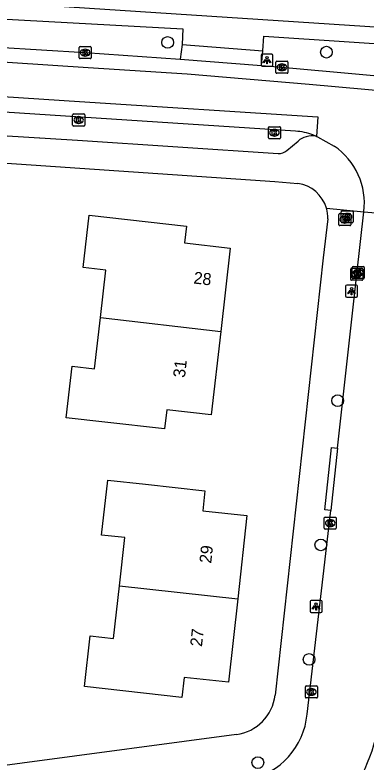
# Model space of a CAD drawing. Extents: x 162398 to 163643, y 386453 to 387397.
# Drawn here: x 162822.3 to 162851.5, y 386535 to 386597.2 of the extents above; entities that cross this region are included whole.
import ezdxf

# ---------------------------------------------------------------- set-up
doc = ezdxf.new("R2010")
doc.units = 0
for name, color, linetype in [('IMGEO_Boom', 7, 'Continuous'), ('IMGEO_Brandkraan', 7, 'Continuous'), ('IMGEO_Kolk', 7, 'Continuous'), ('IMGEO_Lichtpunt', 7, 'Continuous'), ('IMGEO_Pand', 7, 'Continuous'), ('IMGEO_Pand_nummerreeks', 7, 'Continuous'), ('IMGEO_Rijbaan_lokaal_gesloten', 7, 'Continuous'), ('IMGEO_Rijbaan_lokaal_open', 7, 'Continuous'), ('IMGEO_Voetpad_open', 7, 'Continuous')]:
    doc.layers.add(name, color=color, linetype=linetype)

msp = doc.modelspace()

# ---------------------------------------------------------------- linework, layer by layer
at = {"layer": 'IMGEO_Boom'}
for centre in [(162835.01, 386594.914), (162848.244, 386594.102), (162849.181, 386565.089), (162847.78, 386553.08), (162846.801, 386543.543), (162842.53, 386534.956)]:
    msp.add_circle(centre, 0.489, dxfattribs=at)
at = {"layer": 'IMGEO_Brandkraan'}
for p, q in [((162849.54, 386580.896), (162850.392, 386580.896)), ((162849.275, 386579.733), (162849.275, 386580.585)), ((162849.35, 386580.659), (162850.202, 386580.659)), ((162849.465, 386579.97), (162849.465, 386580.822)), ((162849.763, 386580.439), (162849.788, 386580.439)), ((162849.953, 386580.676), (162849.978, 386580.676)), ((162850.276, 386580.585), (162850.276, 386579.733)), ((162850.466, 386580.822), (162850.466, 386579.97)), ((162850.202, 386579.659), (162849.35, 386579.659)), ((162850.392, 386579.896), (162849.54, 386579.896)), ((162849.786, 386579.879), (162849.761, 386579.879)), ((162849.976, 386580.116), (162849.951, 386580.116))]:
    msp.add_line(p, q, dxfattribs=at)
for points in [[(162849.54, 386580.896), (162850.392, 386580.896)], [(162849.275, 386579.733), (162849.275, 386580.585)], [(162849.35, 386580.659), (162850.202, 386580.659)], [(162849.465, 386579.97), (162849.465, 386580.822)], [(162849.623, 386580.359), (162849.623, 386579.959), (162849.836, 386579.959)], [(162849.854, 386580.359), (162849.623, 386580.359)], [(162849.802, 386580.278), (162849.748, 386580.278), (162849.748, 386580.202)], [(162849.813, 386580.596), (162849.813, 386580.196), (162850.026, 386580.196)], [(162850.044, 386580.596), (162849.813, 386580.596)], [(162849.992, 386580.515), (162849.938, 386580.515), (162849.938, 386580.439)], [(162849.938, 386580.439), (162849.991, 386580.439)], [(162850, 386580.363), (162849.938, 386580.363), (162849.938, 386580.282)], [(162849.938, 386580.282), (162850, 386580.282)], [(162850.276, 386580.585), (162850.276, 386579.733)], [(162850.466, 386580.822), (162850.466, 386579.97)], [(162850.202, 386579.659), (162849.35, 386579.659)], [(162850.392, 386579.896), (162849.54, 386579.896)], [(162849.748, 386580.202), (162849.801, 386580.202)], [(162849.81, 386580.126), (162849.748, 386580.126), (162849.748, 386580.045)], [(162849.748, 386580.045), (162849.81, 386580.045)]]:
    msp.add_lwpolyline(points, dxfattribs=at)
for centre, radius, start, end in [((162849.542, 386580.82), 0.0765, 91.55205, 178.44795), ((162849.542, 386580.82), 0.0765, 91.55205, 178.44795), ((162850.39, 386580.82), 0.0765, 1.55205, 88.44795), ((162850.39, 386580.82), 0.0765, 1.55205, 88.44795), ((162849.352, 386580.583), 0.0765, 91.55205, 178.44795), ((162849.352, 386580.583), 0.0765, 91.55205, 178.44795), ((162849.803, 386580.24), 0.0379, 267.82845, 90.93552), ((162849.858, 386580.214), 0.145, 59.4692, 91.53667), ((162849.883, 386580.261), 0.0922, 285.51372, 58.15012), ((162849.993, 386580.477), 0.0379, 267.82845, 90.93552), ((162850.001, 386580.322), 0.0404, 269.87594, 90.50774), ((162850.048, 386580.451), 0.145, 59.4692, 91.53667), ((162850.073, 386580.498), 0.0922, 285.51372, 58.15012), ((162850.078, 386580.306), 0.105, 301.31148, 78.98903), ((162850.2, 386580.583), 0.0765, 1.55205, 88.44795), ((162850.2, 386580.583), 0.0765, 1.55205, 88.44795), ((162849.352, 386579.735), 0.0765, 181.55205, 268.44795), ((162849.352, 386579.735), 0.0765, 181.55205, 268.44795), ((162849.542, 386579.972), 0.0765, 181.55205, 268.44795), ((162849.542, 386579.972), 0.0765, 181.55205, 268.44795), ((162849.811, 386580.085), 0.0404, 269.87594, 90.50774), ((162849.842, 386580.21), 0.251, 268.66757, 293.53466), ((162849.888, 386580.069), 0.105, 301.31148, 78.98903), ((162850.032, 386580.447), 0.251, 268.66757, 293.53466), ((162850.2, 386579.735), 0.0765, 271.55205, 358.44795), ((162850.2, 386579.735), 0.0765, 271.55205, 358.44795), ((162850.39, 386579.972), 0.0765, 271.55205, 358.44795), ((162850.39, 386579.972), 0.0765, 271.55205, 358.44795)]:
    msp.add_arc(centre, radius, start, end, dxfattribs=at)
for centre, major_axis, ratio, start_param, end_param in [((162849.762, 386580.159), (-0.387, 0.002), 0.722429, 4.712389, 7.853982), ((162849.952, 386580.396), (-0.387, 0.002), 0.722429, 4.712389, 7.853982), ((162849.787, 386580.159), (-0.39, 0.002), 0.717154, 1.570796, 4.712389), ((162849.977, 386580.396), (-0.39, 0.002), 0.717154, 1.570796, 4.712389)]:
    msp.add_ellipse(centre, major_axis=major_axis, ratio=ratio, start_param=start_param, end_param=end_param, dxfattribs=at)
at = {"layer": 'IMGEO_Kolk'}
for p, q in [((162827.709, 386594.563), (162828.561, 386594.563)), ((162827.634, 386593.637), (162827.634, 386594.489)), ((162828.122, 386594.343), (162828.147, 386594.343)), ((162828.635, 386594.489), (162828.635, 386593.637)), ((162828.561, 386593.563), (162827.709, 386593.563)), ((162828.145, 386593.783), (162828.12, 386593.783)), ((162844.113, 386593.344), (162844.965, 386593.344)), ((162844.038, 386592.418), (162844.038, 386593.27)), ((162844.526, 386593.124), (162844.551, 386593.124)), ((162845.039, 386593.27), (162845.039, 386592.418)), ((162844.965, 386592.344), (162844.113, 386592.344)), ((162844.549, 386592.564), (162844.524, 386592.564)), ((162827.093, 386588.029), (162827.093, 386588.881)), ((162827.168, 386588.955), (162828.02, 386588.955)), ((162827.581, 386588.735), (162827.606, 386588.735)), ((162828.094, 386588.881), (162828.094, 386588.029)), ((162828.02, 386587.955), (162827.168, 386587.955)), ((162827.604, 386588.175), (162827.579, 386588.175)), ((162843.408, 386586.971), (162843.408, 386587.823)), ((162843.483, 386587.897), (162844.335, 386587.897)), ((162844.409, 386587.823), (162844.409, 386586.971)), ((162843.919, 386587.117), (162843.894, 386587.117)), ((162843.896, 386587.677), (162843.921, 386587.677)), ((162844.335, 386586.897), (162843.483, 386586.897)), ((162850.27, 386575.186), (162850.27, 386576.038)), ((162850.345, 386576.112), (162851.197, 386576.112)), ((162850.4, 386575.323), (162850.4, 386576.175)), ((162850.475, 386576.249), (162851.327, 386576.249)), ((162850.888, 386576.029), (162850.913, 386576.029)), ((162851.271, 386576.038), (162851.271, 386575.186)), ((162851.401, 386576.175), (162851.401, 386575.323)), ((162850.781, 386575.332), (162850.756, 386575.332)), ((162850.758, 386575.892), (162850.783, 386575.892)), ((162850.911, 386575.469), (162850.886, 386575.469)), ((162851.197, 386575.112), (162850.345, 386575.112)), ((162851.327, 386575.249), (162850.475, 386575.249)), ((162848.137, 386555.394), (162848.989, 386555.394)), ((162848.062, 386554.468), (162848.062, 386555.32)), ((162848.55, 386555.174), (162848.575, 386555.174)), ((162849.063, 386555.32), (162849.063, 386554.468)), ((162848.989, 386554.394), (162848.137, 386554.394)), ((162848.573, 386554.614), (162848.548, 386554.614)), ((162846.491, 386540.411), (162846.491, 386541.263)), ((162846.566, 386541.337), (162847.418, 386541.337)), ((162846.979, 386541.117), (162847.004, 386541.117)), ((162847.492, 386541.263), (162847.492, 386540.411)), ((162847.002, 386540.557), (162846.977, 386540.557)), ((162847.418, 386540.337), (162846.566, 386540.337))]:
    msp.add_line(p, q, dxfattribs=at)
for points in [[(162827.709, 386594.563), (162828.561, 386594.563)], [(162827.634, 386593.637), (162827.634, 386594.489)], [(162827.955, 386594.263), (162828.078, 386594.263), (162828.078, 386594.112), (162828.208, 386594.263), (162828.372, 386594.263), (162828.226, 386594.112), (162828.379, 386593.863), (162828.227, 386593.863), (162828.142, 386594.027), (162828.078, 386593.96), (162828.078, 386593.863), (162827.955, 386593.863), (162827.955, 386594.263)], [(162828.635, 386594.489), (162828.635, 386593.637)], [(162828.561, 386593.563), (162827.709, 386593.563)], [(162844.113, 386593.344), (162844.965, 386593.344)], [(162844.038, 386592.418), (162844.038, 386593.27)], [(162844.359, 386593.044), (162844.482, 386593.044), (162844.482, 386592.893), (162844.612, 386593.044), (162844.776, 386593.044), (162844.63, 386592.893), (162844.783, 386592.644), (162844.631, 386592.644), (162844.546, 386592.808), (162844.482, 386592.741), (162844.482, 386592.644), (162844.359, 386592.644), (162844.359, 386593.044)], [(162845.039, 386593.27), (162845.039, 386592.418)], [(162844.965, 386592.344), (162844.113, 386592.344)], [(162827.093, 386588.029), (162827.093, 386588.881)], [(162827.168, 386588.955), (162828.02, 386588.955)], [(162827.414, 386588.655), (162827.537, 386588.655), (162827.537, 386588.504), (162827.667, 386588.655), (162827.831, 386588.655), (162827.685, 386588.504), (162827.838, 386588.255), (162827.686, 386588.255), (162827.601, 386588.419), (162827.537, 386588.352), (162827.537, 386588.255), (162827.414, 386588.255), (162827.414, 386588.655)], [(162828.094, 386588.881), (162828.094, 386588.029)], [(162828.02, 386587.955), (162827.168, 386587.955)], [(162843.408, 386586.971), (162843.408, 386587.823)], [(162843.483, 386587.897), (162844.335, 386587.897)], [(162844.409, 386587.823), (162844.409, 386586.971)], [(162843.729, 386587.597), (162843.852, 386587.597), (162843.852, 386587.446), (162843.982, 386587.597), (162844.146, 386587.597), (162844, 386587.446), (162844.153, 386587.197), (162844.001, 386587.197), (162843.916, 386587.361), (162843.852, 386587.294), (162843.852, 386587.197), (162843.729, 386587.197), (162843.729, 386587.597)], [(162844.335, 386586.897), (162843.483, 386586.897)], [(162850.27, 386575.186), (162850.27, 386576.038)], [(162850.345, 386576.112), (162851.197, 386576.112)], [(162850.4, 386575.323), (162850.4, 386576.175)], [(162850.475, 386576.249), (162851.327, 386576.249)], [(162850.721, 386575.949), (162850.844, 386575.949), (162850.844, 386575.798), (162850.974, 386575.949), (162851.138, 386575.949), (162850.992, 386575.798), (162851.145, 386575.549), (162850.993, 386575.549), (162850.908, 386575.713), (162850.844, 386575.646), (162850.844, 386575.549), (162850.721, 386575.549), (162850.721, 386575.949)], [(162851.271, 386576.038), (162851.271, 386575.186)], [(162851.401, 386576.175), (162851.401, 386575.323)], [(162850.591, 386575.812), (162850.714, 386575.812), (162850.714, 386575.661), (162850.844, 386575.812), (162851.008, 386575.812), (162850.862, 386575.661), (162851.015, 386575.412), (162850.863, 386575.412), (162850.778, 386575.576), (162850.714, 386575.509), (162850.714, 386575.412), (162850.591, 386575.412), (162850.591, 386575.812)], [(162851.197, 386575.112), (162850.345, 386575.112)], [(162851.327, 386575.249), (162850.475, 386575.249)], [(162848.137, 386555.394), (162848.989, 386555.394)], [(162848.062, 386554.468), (162848.062, 386555.32)], [(162848.383, 386555.094), (162848.506, 386555.094), (162848.506, 386554.943), (162848.636, 386555.094), (162848.8, 386555.094), (162848.654, 386554.943), (162848.807, 386554.694), (162848.655, 386554.694), (162848.57, 386554.858), (162848.506, 386554.791), (162848.506, 386554.694), (162848.383, 386554.694), (162848.383, 386555.094)], [(162849.063, 386555.32), (162849.063, 386554.468)], [(162848.989, 386554.394), (162848.137, 386554.394)], [(162846.491, 386540.411), (162846.491, 386541.263)], [(162846.566, 386541.337), (162847.418, 386541.337)], [(162847.492, 386541.263), (162847.492, 386540.411)], [(162846.812, 386541.037), (162846.935, 386541.037), (162846.935, 386540.886), (162847.065, 386541.037), (162847.229, 386541.037), (162847.083, 386540.886), (162847.236, 386540.637), (162847.084, 386540.637), (162846.999, 386540.801), (162846.935, 386540.734), (162846.935, 386540.637), (162846.812, 386540.637), (162846.812, 386541.037)], [(162847.418, 386540.337), (162846.566, 386540.337)]]:
    msp.add_lwpolyline(points, dxfattribs=at)
for centre, start, end in [((162827.711, 386594.487), 91.55205, 178.44795), ((162827.711, 386594.487), 91.55205, 178.44795), ((162828.559, 386594.487), 1.55205, 88.44795), ((162828.559, 386594.487), 1.55205, 88.44795), ((162827.711, 386593.639), 181.55205, 268.44795), ((162827.711, 386593.639), 181.55205, 268.44795), ((162828.559, 386593.639), 271.55205, 358.44795), ((162828.559, 386593.639), 271.55205, 358.44795), ((162844.115, 386593.268), 91.55205, 178.44795), ((162844.115, 386593.268), 91.55205, 178.44795), ((162844.963, 386593.268), 1.55205, 88.44795), ((162844.963, 386593.268), 1.55205, 88.44795), ((162844.115, 386592.42), 181.55205, 268.44795), ((162844.115, 386592.42), 181.55205, 268.44795), ((162844.963, 386592.42), 271.55205, 358.44795), ((162844.963, 386592.42), 271.55205, 358.44795), ((162827.17, 386588.879), 91.55205, 178.44795), ((162827.17, 386588.879), 91.55205, 178.44795), ((162828.018, 386588.879), 1.55205, 88.44795), ((162828.018, 386588.879), 1.55205, 88.44795), ((162827.17, 386588.031), 181.55205, 268.44795), ((162827.17, 386588.031), 181.55205, 268.44795), ((162828.018, 386588.031), 271.55205, 358.44795), ((162828.018, 386588.031), 271.55205, 358.44795), ((162843.485, 386587.821), 91.55205, 178.44795), ((162843.485, 386587.821), 91.55205, 178.44795), ((162844.333, 386587.821), 1.55205, 88.44795), ((162844.333, 386587.821), 1.55205, 88.44795), ((162843.485, 386586.973), 181.55205, 268.44795), ((162843.485, 386586.973), 181.55205, 268.44795), ((162844.333, 386586.973), 271.55205, 358.44795), ((162844.333, 386586.973), 271.55205, 358.44795), ((162850.347, 386576.036), 91.55205, 178.44795), ((162850.347, 386576.036), 91.55205, 178.44795), ((162850.477, 386576.173), 91.55205, 178.44795), ((162850.477, 386576.173), 91.55205, 178.44795), ((162851.195, 386576.036), 1.55205, 88.44795), ((162851.195, 386576.036), 1.55205, 88.44795), ((162851.325, 386576.173), 1.55205, 88.44795), ((162851.325, 386576.173), 1.55205, 88.44795), ((162850.477, 386575.325), 181.55205, 268.44795), ((162850.477, 386575.325), 181.55205, 268.44795), ((162851.325, 386575.325), 271.55205, 358.44795), ((162851.325, 386575.325), 271.55205, 358.44795), ((162850.347, 386575.188), 181.55205, 268.44795), ((162850.347, 386575.188), 181.55205, 268.44795), ((162851.195, 386575.188), 271.55205, 358.44795), ((162851.195, 386575.188), 271.55205, 358.44795), ((162848.139, 386555.318), 91.55205, 178.44795), ((162848.139, 386555.318), 91.55205, 178.44795), ((162848.987, 386555.318), 1.55205, 88.44795), ((162848.987, 386555.318), 1.55205, 88.44795), ((162848.139, 386554.47), 181.55205, 268.44795), ((162848.139, 386554.47), 181.55205, 268.44795), ((162848.987, 386554.47), 271.55205, 358.44795), ((162848.987, 386554.47), 271.55205, 358.44795), ((162846.568, 386541.261), 91.55205, 178.44795), ((162846.568, 386541.261), 91.55205, 178.44795), ((162847.416, 386541.261), 1.55205, 88.44795), ((162847.416, 386541.261), 1.55205, 88.44795), ((162846.568, 386540.413), 181.55205, 268.44795), ((162846.568, 386540.413), 181.55205, 268.44795), ((162847.416, 386540.413), 271.55205, 358.44795), ((162847.416, 386540.413), 271.55205, 358.44795)]:
    msp.add_arc(centre, 0.0765, start, end, dxfattribs=at)
for centre, major_axis, ratio, start_param, end_param in [((162828.121, 386594.063), (-0.387, 0.002), 0.722429, 4.712389, 7.853982), ((162828.146, 386594.063), (-0.39, 0.002), 0.717154, 1.570796, 4.712389), ((162844.525, 386592.844), (-0.387, 0.002), 0.722429, 4.712389, 7.853982), ((162844.55, 386592.844), (-0.39, 0.002), 0.717154, 1.570796, 4.712389), ((162827.58, 386588.455), (-0.387, 0.002), 0.722429, 4.712389, 7.853982), ((162827.605, 386588.455), (-0.39, 0.002), 0.717154, 1.570796, 4.712389), ((162843.895, 386587.397), (-0.387, 0.002), 0.722429, 4.712389, 7.853982), ((162843.92, 386587.397), (-0.39, 0.002), 0.717154, 1.570796, 4.712389), ((162850.887, 386575.749), (-0.387, 0.002), 0.722429, 4.712389, 7.853982), ((162850.912, 386575.749), (-0.39, 0.002), 0.717154, 1.570796, 4.712389), ((162850.757, 386575.612), (-0.387, 0.002), 0.722429, 4.712389, 7.853982), ((162850.782, 386575.612), (-0.39, 0.002), 0.717154, 1.570796, 4.712389), ((162848.549, 386554.894), (-0.387, 0.002), 0.722429, 4.712389, 7.853982), ((162848.574, 386554.894), (-0.39, 0.002), 0.717154, 1.570796, 4.712389), ((162846.978, 386540.837), (-0.387, 0.002), 0.722429, 4.712389, 7.853982), ((162847.003, 386540.837), (-0.39, 0.002), 0.717154, 1.570796, 4.712389)]:
    msp.add_ellipse(centre, major_axis=major_axis, ratio=ratio, start_param=start_param, end_param=end_param, dxfattribs=at)
at = {"layer": 'IMGEO_Lichtpunt'}
for p, q in [((162842.795, 386593.839), (162842.795, 386593.032)), ((162842.795, 386593.839), (162842.795, 386593.032)), ((162843.697, 386593.934), (162842.889, 386593.934)), ((162843.697, 386593.934), (162842.889, 386593.934)), ((162843.791, 386593.032), (162843.791, 386593.839)), ((162843.791, 386593.032), (162843.791, 386593.839)), ((162842.889, 386592.938), (162843.697, 386592.938)), ((162842.889, 386592.938), (162843.697, 386592.938)), ((162850.741, 386574.713), (162849.933, 386574.713)), ((162850.741, 386574.713), (162849.933, 386574.713)), ((162849.839, 386574.618), (162849.839, 386573.811)), ((162849.839, 386574.618), (162849.839, 386573.811)), ((162850.835, 386573.811), (162850.835, 386574.618)), ((162850.835, 386573.811), (162850.835, 386574.618)), ((162849.933, 386573.717), (162850.741, 386573.717)), ((162849.933, 386573.717), (162850.741, 386573.717)), ((162846.883, 386548.358), (162846.883, 386547.551)), ((162846.883, 386548.358), (162846.883, 386547.551)), ((162847.785, 386548.453), (162846.977, 386548.453)), ((162847.785, 386548.453), (162846.977, 386548.453)), ((162847.879, 386547.551), (162847.879, 386548.358)), ((162847.879, 386547.551), (162847.879, 386548.358)), ((162846.977, 386547.457), (162847.785, 386547.457)), ((162846.977, 386547.457), (162847.785, 386547.457))]:
    msp.add_line(p, q, dxfattribs=at)
for points in [[(162843.169, 386593.503), (162843.208, 386593.475), (162843.02, 386593.213), (162842.982, 386593.24), (162843.169, 386593.503)], [(162843.271, 386593.455), (162843.318, 386593.455), (162843.318, 386593.133), (162843.271, 386593.133), (162843.271, 386593.455)], [(162843.381, 386593.475), (162843.419, 386593.502), (162843.606, 386593.24), (162843.567, 386593.212), (162843.381, 386593.475)], [(162850.213, 386574.282), (162850.252, 386574.254), (162850.064, 386573.992), (162850.026, 386574.019), (162850.213, 386574.282)], [(162850.315, 386574.234), (162850.362, 386574.234), (162850.362, 386573.912), (162850.315, 386573.912), (162850.315, 386574.234)], [(162850.425, 386574.254), (162850.463, 386574.281), (162850.65, 386574.019), (162850.611, 386573.991), (162850.425, 386574.254)], [(162847.257, 386548.022), (162847.296, 386547.994), (162847.108, 386547.732), (162847.07, 386547.759), (162847.257, 386548.022)], [(162847.359, 386547.974), (162847.406, 386547.974), (162847.406, 386547.652), (162847.359, 386547.652), (162847.359, 386547.974)], [(162847.469, 386547.994), (162847.507, 386548.021), (162847.694, 386547.759), (162847.655, 386547.731), (162847.469, 386547.994)]]:
    msp.add_lwpolyline(points, dxfattribs=at)
for centre in [(162843.294, 386593.637), (162850.338, 386574.416), (162847.382, 386548.156)]:
    msp.add_circle(centre, 0.0994, dxfattribs=at)
for centre, start, end in [((162842.889, 386593.839), 90, 180), ((162842.889, 386593.839), 90, 180), ((162843.697, 386593.839), 0, 90), ((162843.697, 386593.839), 0, 90), ((162842.889, 386593.032), 180, 270), ((162842.889, 386593.032), 180, 270), ((162843.697, 386593.032), 270, 0), ((162843.697, 386593.032), 270, 360), ((162849.933, 386574.618), 90, 180), ((162849.933, 386574.618), 90, 180), ((162850.741, 386574.618), 0, 90), ((162850.741, 386574.618), 0, 90), ((162849.933, 386573.811), 180, 270), ((162849.933, 386573.811), 180, 270), ((162850.741, 386573.811), 270, 0), ((162850.741, 386573.811), 270, 360), ((162846.977, 386548.358), 90, 180), ((162846.977, 386548.358), 90, 180), ((162847.785, 386548.358), 0, 90), ((162847.785, 386548.358), 0, 90), ((162846.977, 386547.551), 180, 270), ((162846.977, 386547.551), 180, 270), ((162847.785, 386547.551), 270, 0), ((162847.785, 386547.551), 270, 360)]:
    msp.add_arc(centre, 0.0946, start, end, dxfattribs=at)
at = {"layer": 'IMGEO_Pand'}
for points in [[(162829.413, 386572), (162829.866, 386575.947), (162827.977, 386576.164), (162828.478, 386580.532), (162836.572, 386579.603), (162836.414, 386578.23), (162840.227, 386577.793), (162839.43, 386570.852)], [(162839.43, 386570.852), (162838.633, 386563.909), (162834.931, 386564.334), (162834.747, 386562.73), (162829.78, 386563.3), (162826.565, 386563.669), (162827.057, 386567.951), (162828.923, 386567.737), (162829.413, 386572)], [(162829.413, 386572), (162839.43, 386570.852)], [(162830.994, 386549.679), (162831.439, 386553.685), (162829.51, 386553.9), (162830.02, 386558.476), (162833.154, 386558.127), (162838.123, 386557.574), (162837.94, 386555.927), (162841.621, 386555.518), (162840.849, 386548.582)], [(162840.849, 386548.582), (162840.077, 386541.643), (162836.38, 386542.054), (162836.194, 386540.375), (162828.08, 386541.278), (162828.55, 386545.502), (162830.505, 386545.284), (162830.994, 386549.679)], [(162830.994, 386549.679), (162840.849, 386548.582)]]:
    msp.add_lwpolyline(points, dxfattribs=at)
at = {"layer": 'IMGEO_Rijbaan_lokaal_gesloten'}
for points in [[(162729.422, 386596.356), (162742.035, 386595.583), (162758.459, 386594.528), (162779.404, 386593.181), (162792.843, 386592.298), (162810.392, 386591.122), (162821.296, 386590.405), (162827.674, 386589.983), (162847.539, 386588.706), (162847.418, 386587.095)], [(162884.813, 386588.054), (162864.715, 386589.801), (162851.441, 386590.986), (162846.8, 386591.41), (162836.628, 386592.258), (162828.377, 386592.8), (162815.732, 386593.621), (162793.309, 386595.117), (162793.383, 386596.353)], [(162820.841, 386594.51), (162828.135, 386594.063), (162836.05, 386593.531)], [(162836.05, 386593.531), (162842.82, 386593.006)], [(162842.82, 386593.006), (162844.539, 386592.844), (162857.433, 386591.68)], [(162845.666, 386587.525), (162821.37, 386589.103)], [(162847.418, 386587.095), (162847.122, 386587.208)]]:
    msp.add_lwpolyline(points, dxfattribs=at)
msp.add_arc((162845.342, 386582.534), 5.001, 69.15023, 86.28428, dxfattribs=at)
at = {"layer": 'IMGEO_Rijbaan_lokaal_open'}
for points in [[(162847.418, 386587.095), (162847.502, 386587.063), (162848.895, 386586.285)], [(162849.175, 386561.132), (162850.771, 386575.612), (162851.366, 386580.816)], [(162851.366, 386580.816), (162857.311, 386580.324)], [(162849.175, 386561.132), (162848.605, 386555.948)], [(162846.636, 386538.981), (162848.605, 386555.948)]]:
    msp.add_lwpolyline(points, dxfattribs=at)
for centre, radius, start, end in [((162845.625, 386581.515), 5.784, 353.06207, 55.56668), ((162840.51, 386539.565), 6.154, 281.41523, 354.55459), ((162840.137, 386539.774), 12.511, 318.09731, 356.58386)]:
    msp.add_arc(centre, radius, start, end, dxfattribs=at)
at = {"layer": 'IMGEO_Voetpad_open'}
for points in [[(162793.321, 386600.105), (162796.177, 386599.905), (162874.812, 386594.75), (162878.183, 386594.518)], [(162820.916, 386595.714), (162821.025, 386596.875), (162836.278, 386596.048), (162836.234, 386594.736)], [(162842.934, 386594.204), (162843.035, 386595.429), (162857.658, 386594.461), (162857.528, 386592.874)], [(162836.234, 386594.736), (162836.05, 386593.531)], [(162836.234, 386594.736), (162842.934, 386594.204)], [(162842.82, 386593.006), (162842.934, 386594.204)], [(162785.824, 386587.292), (162843.932, 386583.335), (162845.859, 386583.167)], [(162821.202, 386587.174), (162827.484, 386586.769), (162844.212, 386585.667)], [(162844.956, 386585.925), (162845.881, 386586.701)], [(162848.247, 386581.106), (162851.366, 386580.816)], [(162848.354, 386580.219), (162847.968, 386576.967), (162843.962, 386540.573)], [(162848.605, 386555.948), (162848.105, 386556.008), (162848.675, 386561.192), (162849.175, 386561.132)], [(162840.749, 386537.29), (162787.136, 386530.123)]]:
    msp.add_lwpolyline(points, dxfattribs=at)
for centre, radius, start, end in [((162847.052, 386585.325), 1.808, 78.30639, 105.94072), ((162847.049, 386585.335), 1.797, 105.95173, 130.52805), ((162844.257, 386586.739), 1.073, 267.59117, 310.65928), ((162845.486, 386580.321), 2.871, 15.87582, 82.53151), ((162845.47, 386580.321), 2.885, 357.9719, 15.78496), ((162840.246, 386540.996), 3.74, 277.72391, 353.51086)]:
    msp.add_arc(centre, radius, start, end, dxfattribs=at)

# ---------------------------------------------------------------- texts
at = {"layer": 'IMGEO_Pand_nummerreeks'}
for s, rotation, p in [('28', 353.46197, (162837.129, 386574.847)), ('31', 83.45064, (162836.446, 386566.959)), ('29', 83.65029, (162838.639, 386551.507)), ('27', 83.65029, (162837.867, 386544.569))]:
    msp.add_text(s, height=1, rotation=rotation, dxfattribs=at).set_placement(p)

doc.saveas('drawing.dxf')
